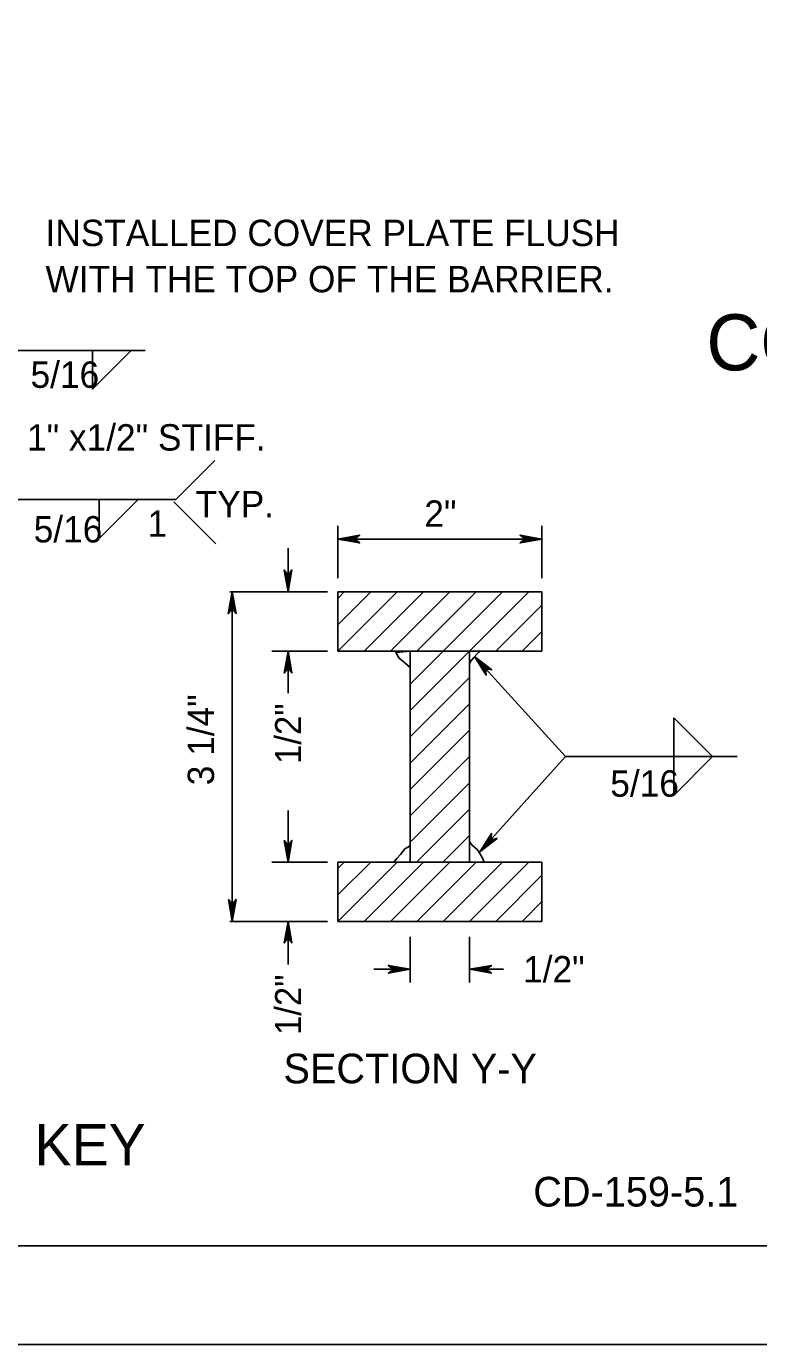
# Model space of a CAD drawing. Extents: x 499883 to 500983, y 499104 to 499764.
# Drawn here: x 500685.6 to 500796.7, y 499103.6 to 499303.5 of the extents above; entities that cross this region are included whole.
import ezdxf

# ---------------------------------------------------------------- set-up
doc = ezdxf.new("R2010")
doc.units = 0
for name, color, linetype in [('1', 7, 'Continuous'), ('24', 7, 'Continuous'), ('39', 7, 'Continuous'), ('41', 7, 'Continuous'), ('5', 7, 'Continuous'), ('60', 7, 'Continuous')]:
    doc.layers.add(name, color=color, linetype=linetype)

msp = doc.modelspace()

# ---------------------------------------------------------------- linework, layer by layer
at = {"layer": '1'}
for p, q in [((499989.94, 499118.64), (500979.94, 499118.64)), ((500982.94, 499103.64), (499934.77, 499103.64))]:
    msp.add_line(p, q, dxfattribs=at)
at = {"layer": '24'}
for points in [[(500753.59, 499207.97), (500755.36, 499205.15), (500755.26, 499206.12), (500756.2, 499205.94), (500753.59, 499207.97), (500753.74, 499207.81), (500755.33, 499205.25), (500755.23, 499206.17), (500756.08, 499206.01), (500753.82, 499207.73), (500753.88, 499207.64), (500755.26, 499205.45), (500755.21, 499206.18), (500755.94, 499206.05), (500753.92, 499207.6), (500754, 499207.53), (500755.2, 499205.62), (500755.19, 499206.2), (500755.78, 499206.14), (500754.22, 499207.3), (500754.34, 499207.16), (500755.15, 499205.8), (500755.16, 499206.22), (500755.62, 499206.19), (500754.35, 499207.12), (500754.46, 499206.99), (500755.1, 499205.99), (500755.11, 499206.31), (500755.44, 499206.28), (500754.58, 499206.88), (500754.67, 499206.74), (500755.05, 499206.13), (500755.09, 499206.32), (500755.34, 499206.3), (500754.74, 499206.69), (500754.97, 499206.28), (500755.02, 499206.41), (500755.25, 499206.35), (500754.83, 499206.62), (500754.98, 499206.34), (500754.97, 499206.5), (500755.11, 499206.44), (500754.94, 499206.48), (500754.98, 499206.41)], [(500754.41, 499178.35), (500757.02, 499180.4), (500756.07, 499180.2), (500756.16, 499181.15), (500754.41, 499178.35), (500754.55, 499178.51), (500756.93, 499180.36), (500756.03, 499180.16), (500756.1, 499181.02), (500754.62, 499178.61), (500754.7, 499178.68), (500756.74, 499180.27), (500756.01, 499180.15), (500756.07, 499180.88), (500754.74, 499178.72), (500754.8, 499178.81), (500756.58, 499180.19), (500756, 499180.13), (500756, 499180.72), (500755.01, 499179.04), (500755.13, 499179.18), (500756.41, 499180.13), (500755.99, 499180.1), (500755.96, 499180.56), (500755.17, 499179.19), (500755.29, 499179.32), (500756.22, 499180.05), (500755.9, 499180.04), (500755.9, 499180.37), (500755.39, 499179.44), (500755.51, 499179.56), (500756.08, 499179.99), (500755.89, 499180.01), (500755.88, 499180.27), (500755.56, 499179.63), (500755.94, 499179.9), (500755.81, 499179.93), (500755.85, 499180.17), (500755.62, 499179.73), (500755.88, 499179.9), (500755.72, 499179.87), (500755.77, 499180.02), (500755.75, 499179.85), (500755.81, 499179.9)], [(500725.3, 499176.81), (500725.88, 499180.09), (500725.3, 499179.31), (500724.73, 499180.07), (500725.3, 499176.81), (500725.29, 499177.03), (500725.83, 499180), (500725.29, 499179.24), (500724.77, 499179.94), (500725.28, 499177.15), (500725.3, 499177.26), (500725.75, 499179.8), (500725.29, 499179.23), (500724.85, 499179.81), (500725.3, 499177.31), (500725.28, 499177.42), (500725.68, 499179.64), (500725.3, 499179.2), (500724.9, 499179.65), (500725.28, 499177.73), (500725.28, 499177.92), (500725.6, 499179.47), (500725.31, 499179.17), (500724.98, 499179.49), (500725.3, 499177.95), (500725.31, 499178.12), (500725.51, 499179.29), (500725.28, 499179.07), (500725.06, 499179.31), (500725.3, 499178.29), (500725.31, 499178.45), (500725.45, 499179.15), (500725.29, 499179.04), (500725.12, 499179.23), (500725.3, 499178.54), (500725.41, 499178.99), (500725.28, 499178.93), (500725.16, 499179.13), (500725.28, 499178.65), (500725.36, 499178.95), (500725.26, 499178.83), (500725.2, 499178.97), (500725.29, 499178.83), (500725.31, 499178.9)], [(500725.3, 499167.82), (500724.72, 499164.55), (500725.3, 499165.33), (500725.87, 499164.56), (500725.3, 499167.82), (500725.3, 499167.6), (500724.76, 499164.64), (500725.31, 499165.39), (500725.82, 499164.7), (500725.31, 499167.49), (500725.3, 499167.38), (500724.85, 499164.84), (500725.3, 499165.41), (500725.75, 499164.82), (500725.3, 499167.33), (500725.31, 499167.22), (500724.91, 499165), (500725.3, 499165.43), (500725.7, 499164.99), (500725.31, 499166.9), (500725.31, 499166.72), (500725, 499165.16), (500725.29, 499165.46), (500725.61, 499165.14), (500725.3, 499166.68), (500725.29, 499166.51), (500725.09, 499165.34), (500725.31, 499165.57), (500725.54, 499165.32), (500725.3, 499166.35), (500725.28, 499166.18), (500725.15, 499165.48), (500725.31, 499165.6), (500725.48, 499165.41), (500725.3, 499166.1), (500725.19, 499165.64), (500725.31, 499165.71), (500725.44, 499165.51), (500725.31, 499165.98), (500725.24, 499165.68), (500725.34, 499165.81), (500725.4, 499165.66), (500725.31, 499165.81), (500725.29, 499165.73)], [(500725.3, 499167.82), (500724.72, 499164.55), (500725.3, 499165.33), (500725.87, 499164.56), (500725.3, 499167.82), (500725.3, 499167.6), (500724.76, 499164.64), (500725.31, 499165.39), (500725.82, 499164.7), (500725.31, 499167.49), (500725.3, 499167.38), (500724.85, 499164.84), (500725.3, 499165.41), (500725.75, 499164.82), (500725.3, 499167.33), (500725.31, 499167.22), (500724.91, 499165), (500725.3, 499165.43), (500725.7, 499164.99), (500725.31, 499166.9), (500725.31, 499166.72), (500725, 499165.16), (500725.29, 499165.46), (500725.61, 499165.14), (500725.3, 499166.68), (500725.29, 499166.51), (500725.09, 499165.34), (500725.31, 499165.57), (500725.54, 499165.32), (500725.3, 499166.35), (500725.28, 499166.18), (500725.15, 499165.48), (500725.31, 499165.6), (500725.48, 499165.41), (500725.3, 499166.1), (500725.19, 499165.64), (500725.31, 499165.71), (500725.44, 499165.51), (500725.31, 499165.98), (500725.24, 499165.68), (500725.34, 499165.81), (500725.4, 499165.66), (500725.31, 499165.81), (500725.29, 499165.73)]]:
    msp.add_lwpolyline(points, dxfattribs=at)
at = {"layer": '41'}
for points in [[(499934.77, 499763.64), (500982.94, 499763.64), (500982.94, 499103.64), (499934.77, 499103.64)], [(499989.94, 499748.64), (500979.94, 499748.64), (500979.94, 499118.64), (499989.94, 499118.64)]]:
    msp.add_lwpolyline(points, close=True, dxfattribs=at)
at = {"layer": '5'}
for p, q in [((500703.62, 499254.38), (500682.22, 499254.38)), ((500701.51, 499254.38), (500695.62, 499248.49)), ((500695.62, 499254.38), (500695.62, 499248.49)), ((500714.18, 499237.67), (500708.29, 499231.78)), ((500708.29, 499231.78), (500683.27, 499231.78)), ((500702.57, 499231.78), (500696.67, 499225.89)), ((500696.67, 499231.78), (500696.67, 499225.89)), ((500707.96, 499231.44), (500714.35, 499225.05)), ((500732.84, 499219.86), (500732.84, 499227.77)), ((500763.82, 499219.86), (500763.82, 499227.77)), ((500732.84, 499225.78), (500763.82, 499225.78)), ((500725.3, 499217.78), (500725.3, 499224.39)), ((500731.29, 499217.78), (500716.49, 499217.78)), ((500716.83, 499167.82), (500716.83, 499217.78)), ((500732.84, 499217.78), (500732.84, 499208.79)), ((500732.84, 499208.79), (500741.84, 499217.78)), ((500732.84, 499212.79), (500737.84, 499217.78)), ((500732.84, 499216.78), (500733.84, 499217.78)), ((500732.84, 499217.78), (500763.82, 499217.78)), ((500736.84, 499208.79), (500745.83, 499217.78)), ((500740.84, 499208.79), (500749.83, 499217.78)), ((500744.84, 499208.79), (500753.83, 499217.78)), ((500748.83, 499208.79), (500757.83, 499217.78)), ((500752.83, 499208.79), (500761.82, 499217.78)), ((500763.82, 499217.78), (500763.82, 499208.79)), ((500756.83, 499208.79), (500763.82, 499215.78)), ((500760.82, 499208.79), (500763.82, 499211.79)), ((500731.29, 499208.79), (500722.85, 499208.79)), ((500725.3, 499202.4), (500725.3, 499208.79)), ((500732.84, 499208.79), (500763.82, 499208.79)), ((500743.84, 499203.8), (500748.83, 499208.79)), ((500743.84, 499199.8), (500752.83, 499208.79)), ((500743.84, 499208.79), (500743.84, 499176.81)), ((500752.83, 499208.79), (500752.83, 499176.81)), ((500767.37, 499192.8), (500753.59, 499207.97)), ((500743.84, 499195.8), (500752.83, 499204.79)), ((500743.84, 499191.8), (500752.83, 499200.8)), ((500789.7, 499192.8), (500783.81, 499198.69)), ((500783.81, 499192.8), (500783.81, 499198.69)), ((500743.84, 499187.8), (500752.83, 499196.8)), ((500743.84, 499183.81), (500752.83, 499192.8)), ((500767.37, 499192.8), (500754.41, 499178.35)), ((500793.44, 499192.8), (500767.37, 499192.8)), ((500789.7, 499192.8), (500783.81, 499186.91)), ((500783.81, 499192.8), (500783.81, 499186.91)), ((500743.84, 499179.81), (500752.83, 499188.8)), ((500725.3, 499184.61), (500725.3, 499176.81)), ((500744.81, 499176.78), (500752.83, 499184.81)), ((500748.79, 499176.78), (500752.8, 499180.78)), ((500731.29, 499176.81), (500722.85, 499176.81)), ((500732.84, 499176.81), (500732.84, 499167.82)), ((500732.84, 499167.82), (500741.84, 499176.81)), ((500732.84, 499171.82), (500737.84, 499176.81)), ((500732.84, 499175.81), (500733.84, 499176.81)), ((500732.84, 499176.81), (500763.82, 499176.81)), ((500736.84, 499167.82), (500745.83, 499176.81)), ((500740.84, 499167.82), (500749.83, 499176.81)), ((500744.84, 499167.82), (500753.83, 499176.81)), ((500748.83, 499167.82), (500757.83, 499176.81)), ((500752.83, 499167.82), (500761.82, 499176.81)), ((500763.82, 499176.81), (500763.82, 499167.82)), ((500756.83, 499167.82), (500763.82, 499174.81)), ((500760.82, 499167.82), (500763.82, 499170.82)), ((500731.29, 499167.82), (500716.49, 499167.82)), ((500725.3, 499167.82), (500725.3, 499161.29)), ((500732.84, 499167.82), (500763.82, 499167.82)), ((500743.84, 499165.49), (500743.84, 499158.56)), ((500752.83, 499165.49), (500752.83, 499158.56)), ((500738.32, 499160.56), (500743.84, 499160.56)), ((500752.83, 499160.56), (500757.96, 499160.56))]:
    msp.add_line(p, q, dxfattribs=at)
for points in [[(500732.84, 499225.78), (500736.17, 499225.19), (500735.37, 499225.78), (500736.15, 499226.35), (500732.84, 499225.78), (500733.06, 499225.78), (500736.07, 499225.23), (500735.31, 499225.78), (500736.02, 499226.31), (500733.18, 499225.79), (500733.29, 499225.78), (500735.87, 499225.32), (500735.29, 499225.78), (500735.89, 499226.23), (500733.35, 499225.78), (500733.46, 499225.79), (500735.71, 499225.39), (500735.27, 499225.78), (500735.72, 499226.18), (500733.78, 499225.79), (500733.96, 499225.79), (500735.54, 499225.47), (500735.24, 499225.77), (500735.57, 499226.1), (500734, 499225.78), (500734.17, 499225.77), (500735.36, 499225.56), (500735.13, 499225.79), (500735.38, 499226.02), (500734.34, 499225.78), (500734.51, 499225.76), (500735.22, 499225.62), (500735.1, 499225.78), (500735.3, 499225.96), (500734.59, 499225.78), (500735.06, 499225.67), (500734.99, 499225.79), (500735.19, 499225.92), (500734.71, 499225.79), (500735.01, 499225.72), (500734.89, 499225.82), (500735.03, 499225.88), (500734.89, 499225.78), (500734.96, 499225.77)], [(500763.82, 499225.78), (500760.5, 499226.36), (500761.29, 499225.78), (500760.51, 499225.2), (500763.82, 499225.78), (500763.6, 499225.77), (500760.59, 499226.32), (500761.35, 499225.77), (500760.65, 499225.24), (500763.48, 499225.76), (500763.37, 499225.78), (500760.79, 499226.23), (500761.37, 499225.77), (500760.78, 499225.32), (500763.32, 499225.78), (500763.21, 499225.76), (500760.96, 499226.17), (500761.39, 499225.78), (500760.95, 499225.37), (500762.89, 499225.76), (500762.7, 499225.76), (500761.12, 499226.08), (500761.43, 499225.79), (500761.1, 499225.45), (500762.67, 499225.78), (500762.49, 499225.79), (500761.3, 499225.99), (500761.53, 499225.76), (500761.28, 499225.53), (500762.33, 499225.78), (500762.16, 499225.79), (500761.45, 499225.93), (500761.56, 499225.77), (500761.37, 499225.59), (500762.07, 499225.78), (500761.61, 499225.89), (500761.67, 499225.76), (500761.47, 499225.63), (500761.96, 499225.76), (500761.65, 499225.84), (500761.78, 499225.74), (500761.63, 499225.68), (500761.78, 499225.77), (500761.7, 499225.79)], [(500725.3, 499217.78), (500725.89, 499221.11), (500725.3, 499220.31), (500724.72, 499221.09), (500725.3, 499217.78), (500725.29, 499218), (500725.84, 499221.01), (500725.29, 499220.25), (500724.77, 499220.95), (500725.28, 499218.12), (500725.3, 499218.23), (500725.76, 499220.81), (500725.29, 499220.23), (500724.84, 499220.83), (500725.3, 499218.28), (500725.28, 499218.39), (500725.69, 499220.65), (500725.3, 499220.21), (500724.89, 499220.66), (500725.28, 499218.72), (500725.28, 499218.9), (500725.61, 499220.48), (500725.31, 499220.17), (500724.98, 499220.5), (500725.3, 499218.94), (500725.31, 499219.11), (500725.51, 499220.3), (500725.28, 499220.07), (500725.05, 499220.32), (500725.3, 499219.28), (500725.32, 499219.44), (500725.45, 499220.16), (500725.29, 499220.04), (500725.11, 499220.23), (500725.3, 499219.53), (500725.41, 499220), (500725.28, 499219.93), (500725.15, 499220.13), (500725.28, 499219.65), (500725.36, 499219.95), (500725.26, 499219.82), (500725.2, 499219.97), (500725.29, 499219.83), (500725.31, 499219.9)], [(500716.83, 499217.78), (500716.24, 499214.46), (500716.83, 499215.25), (500717.41, 499214.48), (500716.83, 499217.78), (500716.84, 499217.56), (500716.29, 499214.55), (500716.84, 499215.31), (500717.36, 499214.61), (500716.85, 499217.44), (500716.83, 499217.33), (500716.37, 499214.75), (500716.84, 499215.33), (500717.29, 499214.74), (500716.83, 499217.28), (500716.85, 499217.17), (500716.44, 499214.92), (500716.83, 499215.36), (500717.24, 499214.91), (500716.85, 499216.85), (500716.85, 499216.66), (500716.53, 499215.08), (500716.82, 499215.39), (500717.15, 499215.06), (500716.83, 499216.63), (500716.82, 499216.45), (500716.62, 499215.26), (500716.85, 499215.49), (500717.08, 499215.25), (500716.83, 499216.29), (500716.82, 499216.12), (500716.68, 499215.41), (500716.84, 499215.53), (500717.02, 499215.33), (500716.83, 499216.03), (500716.72, 499215.57), (500716.85, 499215.64), (500716.98, 499215.43), (500716.85, 499215.92), (500716.77, 499215.61), (500716.87, 499215.74), (500716.93, 499215.59), (500716.84, 499215.74), (500716.82, 499215.66)], [(500725.3, 499208.79), (500724.71, 499205.47), (500725.3, 499206.26), (500725.88, 499205.48), (500725.3, 499208.79), (500725.3, 499208.57), (500724.75, 499205.56), (500725.31, 499206.32), (500725.83, 499205.62), (500725.31, 499208.45), (500725.3, 499208.34), (500724.84, 499205.76), (500725.3, 499206.34), (500725.76, 499205.74), (500725.3, 499208.29), (500725.31, 499208.18), (500724.91, 499205.92), (500725.3, 499206.36), (500725.7, 499205.91), (500725.32, 499207.86), (500725.31, 499207.67), (500724.99, 499206.09), (500725.29, 499206.4), (500725.62, 499206.07), (500725.3, 499207.64), (500725.29, 499207.46), (500725.09, 499206.27), (500725.32, 499206.5), (500725.54, 499206.25), (500725.3, 499207.29), (500725.28, 499207.13), (500725.15, 499206.41), (500725.31, 499206.53), (500725.48, 499206.34), (500725.3, 499207.04), (500725.19, 499206.58), (500725.31, 499206.64), (500725.44, 499206.44), (500725.32, 499206.92), (500725.24, 499206.62), (500725.34, 499206.75), (500725.4, 499206.6), (500725.31, 499206.75), (500725.29, 499206.67)], [(500716.83, 499167.82), (500717.42, 499171.14), (500716.83, 499170.35), (500716.25, 499171.13), (500716.83, 499167.82), (500716.83, 499168.04), (500717.38, 499171.05), (500716.83, 499170.29), (500716.3, 499170.99), (500716.82, 499168.16), (500716.83, 499168.27), (500717.29, 499170.85), (500716.83, 499170.27), (500716.37, 499170.87), (500716.83, 499168.32), (500716.82, 499168.43), (500717.22, 499170.69), (500716.83, 499170.25), (500716.43, 499170.7), (500716.82, 499168.75), (500716.82, 499168.94), (500717.14, 499170.52), (500716.84, 499170.21), (500716.51, 499170.54), (500716.83, 499168.97), (500716.84, 499169.15), (500717.05, 499170.34), (500716.82, 499170.11), (500716.59, 499170.36), (500716.83, 499169.31), (500716.85, 499169.48), (500716.99, 499170.19), (500716.83, 499170.08), (500716.65, 499170.27), (500716.83, 499169.57), (500716.94, 499170.03), (500716.82, 499169.97), (500716.69, 499170.17), (500716.82, 499169.69), (500716.89, 499169.99), (500716.79, 499169.86), (500716.73, 499170.01), (500716.83, 499169.86), (500716.84, 499169.94)], [(500743.84, 499160.56), (500740.51, 499161.14), (500741.31, 499160.56), (500740.53, 499159.98), (500743.84, 499160.56), (500743.61, 499160.55), (500740.61, 499161.1), (500741.37, 499160.55), (500740.66, 499160.02), (500743.5, 499160.54), (500743.38, 499160.56), (500740.81, 499161.01), (500741.38, 499160.55), (500740.79, 499160.1), (500743.33, 499160.56), (500743.22, 499160.54), (500740.97, 499160.95), (500741.41, 499160.56), (500740.96, 499160.15), (500742.9, 499160.54), (500742.72, 499160.54), (500741.14, 499160.86), (500741.44, 499160.57), (500741.11, 499160.23), (500742.68, 499160.56), (500742.5, 499160.57), (500741.32, 499160.77), (500741.55, 499160.54), (500741.3, 499160.31), (500742.34, 499160.56), (500742.17, 499160.57), (500741.46, 499160.71), (500741.58, 499160.55), (500741.38, 499160.37), (500742.09, 499160.56), (500741.62, 499160.67), (500741.69, 499160.54), (500741.49, 499160.41), (500741.97, 499160.54), (500741.67, 499160.62), (500741.79, 499160.52), (500741.65, 499160.46), (500741.79, 499160.55), (500741.72, 499160.57)], [(500752.83, 499160.56), (500756.15, 499159.97), (500755.36, 499160.56), (500756.14, 499161.13), (500752.83, 499160.56), (500753.05, 499160.56), (500756.06, 499160.01), (500755.3, 499160.56), (500756, 499161.09), (500753.17, 499160.57), (500753.28, 499160.56), (500755.86, 499160.1), (500755.28, 499160.56), (500755.87, 499161.01), (500753.33, 499160.56), (500753.44, 499160.57), (500755.69, 499160.17), (500755.26, 499160.56), (500755.7, 499160.96), (500753.76, 499160.57), (500753.95, 499160.57), (500755.53, 499160.25), (500755.22, 499160.55), (500755.55, 499160.88), (500753.98, 499160.56), (500754.16, 499160.55), (500755.35, 499160.34), (500755.12, 499160.57), (500755.37, 499160.8), (500754.32, 499160.56), (500754.49, 499160.54), (500755.2, 499160.4), (500755.09, 499160.56), (500755.28, 499160.74), (500754.58, 499160.56), (500755.04, 499160.45), (500754.98, 499160.57), (500755.18, 499160.7), (500754.69, 499160.57), (500755, 499160.5), (500754.87, 499160.6), (500755.02, 499160.66), (500754.87, 499160.56), (500754.95, 499160.55)]]:
    msp.add_lwpolyline(points, dxfattribs=at)
at = {"layer": '60'}
for points in [[(500743.84, 499208.79), (500741.64, 499208.6), (500742.16, 499207.72), (500743.04, 499207.02), (500743.83, 499206.31)], [(500752.83, 499208.79), (500752.83, 499206.93), (500753.05, 499207.28), (500753.49, 499207.81), (500753.93, 499208.33), (500754.46, 499208.79)], [(500743.84, 499176.81), (500742.16, 499176.81), (500741.37, 499176.81), (500741.81, 499177.33), (500742.34, 499177.95), (500743.04, 499178.83), (500743.84, 499179.27)], [(500752.83, 499176.81), (500755.07, 499176.81), (500754.81, 499177.42), (500754.37, 499178.12), (500754.02, 499178.65), (500753.23, 499179.35), (500752.83, 499179.88)]]:
    msp.add_lwpolyline(points, close=True, dxfattribs=at)

# ---------------------------------------------------------------- texts
at = {"layer": '39'}
msp.add_text('CD-159-5.1', height=4.5, dxfattribs=at).set_placement((500762.5, 499124.58))
at = {"layer": '5'}
for s, height, p in [('INSTALLED COVER PLATE FLUSH ', 4, (500688.51, 499270.2)), ('WITH THE TOP OF THE BARRIER.', 4, (500688.51, 499263.2)), ('CONSTRUCTION BARRIER CURB', 8.5, (500788.75, 499251.36)), ('5/16', 4, (500686.24, 499248.71)), ('1" x1/2" STIFF.', 4, (500685.71, 499239.2)), ('TYP.', 4, (500711.29, 499229.08)), ('2"', 4, (500745.98, 499227.64)), ('5/16', 4, (500686.72, 499225.27)), ('1', 4, (500703.98, 499226.12)), ('5/16', 4, (500774.18, 499186.72)), ('1/2"', 4, (500760.96, 499158.56)), ('SECTION Y-Y', 4.5, (500724.61, 499143.26)), ('CONNECTION KEY', 6.2992, (500627.89, 499130.8))]:
    msp.add_text(s, height=height, dxfattribs=at).set_placement(p)
for s, height, p in [('3 1/4"', 4, (500714.08, 499188.45)), ('1/2"', 3.937, (500727.27, 499191.68)), ('1/2"', 3.937, (500727.27, 499150.58))]:
    msp.add_text(s, height=height, rotation=90, dxfattribs=at).set_placement(p)

doc.saveas('drawing.dxf')
